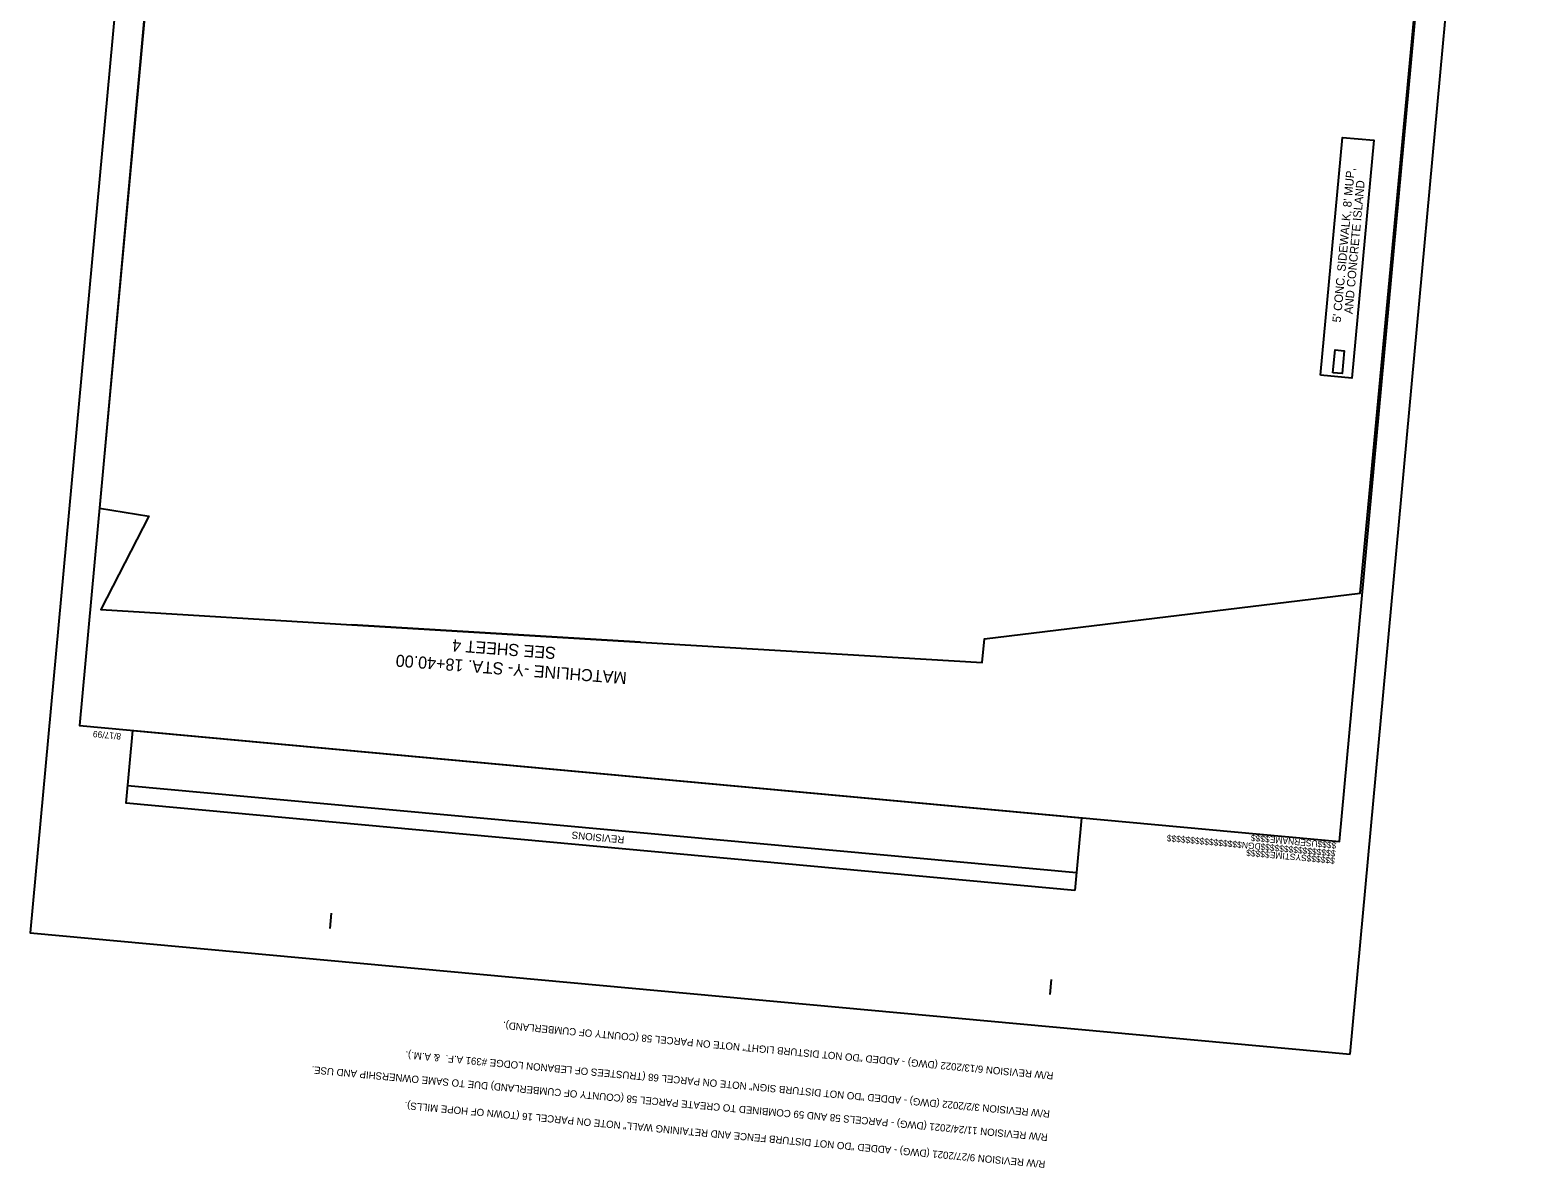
# Model space of a CAD drawing. Extents: x 2011671 to 2012922, y 444832 to 446720.
# Drawn here: x 2011671 to 2012922, y 444832 to 445776 of the extents above; entities that cross this region are included whole.
import ezdxf

# ---------------------------------------------------------------- set-up
doc = ezdxf.new("R2010")
doc.units = 0
for name, color, linetype in [('Matchline', 7, 'Continuous'), ('Matchline Text', 7, 'Continuous'), ('Old_Level_1', 7, 'Continuous'), ('Prop DSN Text', 7, 'Continuous'), ('Prop Shade Medium', 7, 'Continuous'), ('Sheet Block Revision CELL', 7, 'Continuous'), ('Sheet Block System Information CELL', 7, 'Continuous'), ('Sheet Clip Boundary CELL', 7, 'Continuous'), ('Sheet Plan And Profile CELL', 7, 'Continuous'), ('Sheet Plot Border Outside CELL', 7, 'Continuous')]:
    doc.layers.add(name, color=color, linetype=linetype)

msp = doc.modelspace()

# ---------------------------------------------------------------- linework, layer by layer
at = {"layer": 'Matchline'}
msp.add_line((2012177, 445268.5), (2011937.4, 445282.9), dxfattribs=at)
at = {"layer": 'Old_Level_1'}
msp.add_lwpolyline([(2012741.3, 445490.1), (2012759.5, 445687.4), (2012785.4, 445685.1), (2012767.3, 445487.7)], close=True, dxfattribs=at)
at = {"layer": 'Prop Shade Medium'}
msp.add_lwpolyline([(2012751.5, 445492.1), (2012753.3, 445511.1), (2012760.9, 445510.4), (2012759.1, 445491.4)], close=True, dxfattribs=at)
at = {"layer": 'Sheet Block Revision CELL'}
msp.add_line((2012538.7, 445077.1), (2011751.4, 445149.5), dxfattribs=at)
msp.add_lwpolyline([(2012537.4, 445062.6), (2011750.1, 445135), (2011755.6, 445195.3), (2012542.9, 445122.9)], close=True, dxfattribs=at)
at = {"layer": 'Sheet Block System Information CELL'}
msp.add_line((2012757, 445103.2), (2012757, 445103.2), dxfattribs=at)
at = {"layer": 'Sheet Clip Boundary CELL'}
msp.add_lwpolyline([(2011937.4, 445282.9), (2012177, 445268.5), (2012460.6, 445251.6), (2012462.4, 445271.2), (2012774, 445309.1), (2012872.6, 446360.1), (2012827.8, 446363.7), (2012831.1, 446402.1), (2012750.7, 446410.1), (2012511.4, 446429.2), (2011895.9, 446477), (2011878.6, 446288.5), (2011811.3, 446294.7), (2011728, 445379.8), (2011768.9, 445373.1), (2011729.3, 445295.7)], close=True, dxfattribs=at)
at = {"layer": 'Sheet Plan And Profile CELL'}
for p, q in [((2012757, 445103.2), (2012757, 445103.2)), ((2012757, 445103.2), (2012757, 445103.2)), ((2012757, 445103.2), (2012757, 445103.2)), ((2012757, 445103.2), (2012757, 445103.2)), ((2012757, 445103.2), (2012757, 445103.2)), ((2011919.4, 445031.1), (2011920.6, 445043.6)), ((2012516.9, 444976.2), (2012518, 444988.6))]:
    msp.add_line(p, q, dxfattribs=at)
msp.add_lwpolyline([(2011848.8, 446693.1), (2011711.5, 445199.4), (2012757, 445103.2), (2012894.4, 446596.9)], close=True, dxfattribs=at)
at = {"layer": 'Sheet Plot Border Outside CELL'}
msp.add_lwpolyline([(2012765.9, 444926.7), (2012921.6, 446619.5), (2011826.2, 446720.2), (2011670.5, 445027.4)], close=True, dxfattribs=at)

# ---------------------------------------------------------------- texts
at = {"layer": 'Matchline Text'}
for s, p in [('SEE SHEET 4', (2012107.1, 445264.4)), ('MATCHLINE -Y- STA. 18+40.00', (2012165.9, 445243.7))]:
    msp.add_text(s, height=10, rotation=175.6366, dxfattribs=at).set_placement(p)
at = {"layer": 'Old_Level_1'}
for s, p in [('R/W REVISION 6/13/2022 (DWG) - ADDED "DO NOT DISTURB LIGHT" NOTE ON PARCEL 58 (COUNTY OF CUMBERLAND).', (2012519.8, 444911.7)), ('R/W REVISION 3/2/2022 (DWG) - ADDED "DO NOT DISTURB SIGN" NOTE ON PARCEL 68 (TRUSTEES OF LEBANON LODGE #391 A.F.  & A.M.).', (2012516.9, 444880)), ('R/W REVISION 11/24/2021 (DWG) - PARCELS 58 AND 59 COMBINED TO CREATE PARCEL 58 (COUNTY OF CUMBERLAND) DUE TO SAME OWNERSHIP AND USE.', (2012515.1, 444860.6)), ('R/W REVISION 9/27/2021 (DWG) - ADDED "DO NOT DISTURB FENCE AND RETAINING WALL" NOTE ON PARCEL 16 (TOWN OF HOPE MILLS).', (2012513.1, 444838.3))]:
    msp.add_text(s, height=6, rotation=174.7467, dxfattribs=at).set_placement(p)
at = {"layer": 'Prop DSN Text'}
for s, p in [("5' CONC. SIDEWALK, 8' MUP,", (2012758, 445533.6)), ('AND CONCRETE ISLAND', (2012767.8, 445540.6))]:
    msp.add_text(s, height=7, rotation=84.7467, dxfattribs=at).set_placement(p)
at = {"layer": 'Sheet Block Revision CELL'}
msp.add_text('REVISIONS', height=6, rotation=174.7467, dxfattribs=at).set_placement((2012163.8, 445107.5))
at = {"layer": 'Sheet Block System Information CELL'}
for s, p in [('$$$$$$$$$$$$$$$$DGN$$$$$$$$$$$$$$$$', (2012754, 445095.8)), ('$$$$USERNAME$$$$', (2012754.6, 445102.4)), ('$$$$$$SYSTIME$$$$$', (2012753.4, 445089.8))]:
    msp.add_text(s, height=5.25, rotation=174.7467, dxfattribs=at).set_placement(p)
at = {"layer": 'Sheet Plan And Profile CELL'}
msp.add_text('8/17/99', height=5.25, rotation=174.7467, dxfattribs=at).set_placement((2011746.2, 445192.9))

doc.saveas('drawing.dxf')
